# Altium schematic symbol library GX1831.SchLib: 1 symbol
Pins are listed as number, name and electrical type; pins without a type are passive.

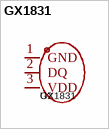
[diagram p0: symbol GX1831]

## GX1831
designator U?
footprint TO-92-3_L4.9-W3.7-P1.27-L
pins: 1 GND, 2 DQ, 3 VDD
